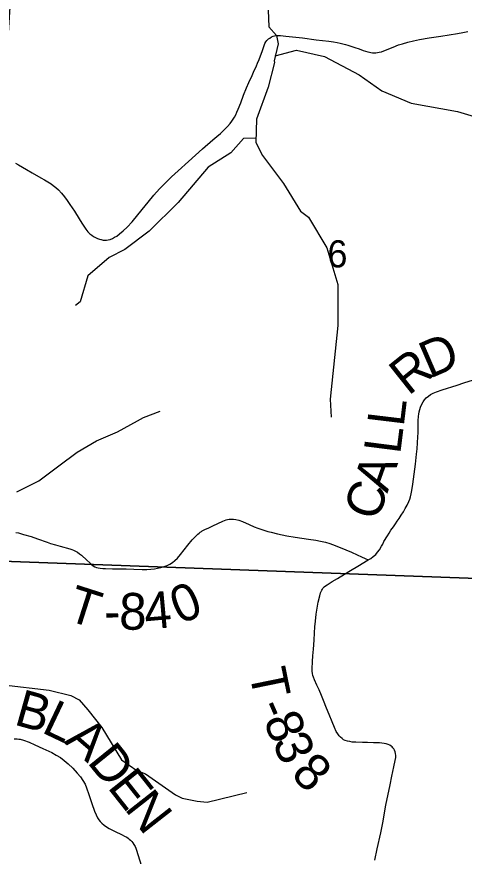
# Model space of a CAD drawing. Extents: x 0 to 34, y 0 to 22.
# Drawn here: x 6.26 to 6.952, y 17.839 to 19.136 of the extents above; entities that cross this region are included whole.
import ezdxf

# ---------------------------------------------------------------- set-up
doc = ezdxf.new("R2010")
doc.units = 0
for name, color, linetype in [('GM_X_County_Road', 7, 'Continuous'), ('GM_X_County_Road_Text', 7, 'Continuous'), ('GM_X_Minor_River', 7, 'Continuous'), ('GM_X_Section', 7, 'Continuous'), ('GM_X_Section_Text', 7, 'Continuous'), ('GM_X_Township_Road', 7, 'Continuous'), ('GM_X_Township_Road_Text', 7, 'Continuous')]:
    doc.layers.add(name, color=color, linetype=linetype)

msp = doc.modelspace()

# ---------------------------------------------------------------- linework, layer by layer
at = {"layer": 'GM_X_County_Road'}
msp.add_lwpolyline([(6.2558, 18.0204), (6.2601, 18.0202), (6.2627, 18.0199), (6.2649, 18.0194), (6.2703, 18.0179), (6.2786, 18.0149), (6.2876, 18.011), (6.2997, 18.0054), (6.3138, 17.9989), (6.3208, 17.9951), (6.3271, 17.9913), (6.333, 17.9869), (6.339, 17.9816), (6.3461, 17.9747), (6.3533, 17.9671), (6.358, 17.9613), (6.3619, 17.9558), (6.3652, 17.9499), (6.3677, 17.9443), (6.3712, 17.9342), (6.3758, 17.9203), (6.3801, 17.9086), (6.3824, 17.9027), (6.3847, 17.8982), (6.3867, 17.895), (6.3887, 17.8925), (6.3914, 17.8897), (6.3947, 17.8868), (6.3983, 17.8843), (6.4026, 17.8817), (6.4109, 17.8773), (6.4227, 17.8717), (6.4262, 17.8699), (6.4296, 17.8681), (6.4318, 17.8667), (6.4337, 17.8653), (6.4355, 17.8637), (6.4375, 17.8616), (6.4391, 17.8597), (6.4408, 17.8571), (6.4425, 17.854), (6.4437, 17.8513), (6.4449, 17.8483), (6.4521, 17.8252)], dxfattribs=at)
at = {"layer": 'GM_X_Minor_River'}
for points in [[(6.6482, 19.1461), (6.6494, 19.1199), (6.6611, 19.107), (6.6638, 19.0937), (6.6578, 19.0675), (6.6581, 19.0652), (6.6483, 19.0268), (6.6302, 18.9774), (6.6295, 18.9416), (6.6394, 18.9215), (6.6719, 18.8782), (6.6984, 18.8354), (6.7109, 18.8259), (6.7393, 18.7787)], [(6.6593, 19.0751), (6.6921, 19.0842), (6.7353, 19.0745), (6.7889, 19.0462), (6.8244, 19.0211), (6.8696, 19.0022), (6.9414, 18.9893), (6.9875, 18.9753), (7.0485, 18.9684), (7.0623, 18.9634), (7.0755, 18.9607)], [(6.6297, 18.9482), (6.6102, 18.9478), (6.5906, 18.9253), (6.5555, 18.9031), (6.5091, 18.849), (6.4646, 18.8043), (6.4269, 18.776), (6.4026, 18.7638), (6.3694, 18.7355), (6.3575, 18.6952), (6.3503, 18.6895)], [(6.7392, 18.7787), (6.7559, 18.7219), (6.7563, 18.6588), (6.7442, 18.5449), (6.7456, 18.5172)], [(6.2596, 18.4018), (6.2936, 18.4186), (6.3245, 18.4419), (6.3529, 18.4632), (6.3827, 18.4808), (6.4156, 18.4946), (6.4462, 18.5117), (6.4557, 18.5167), (6.4814, 18.5263)], [(6.0056, 18.2259), (6.014, 18.201), (6.037, 18.1745), (6.0614, 18.1595), (6.1024, 18.1517), (6.1803, 18.1301), (6.2389, 18.1034), (6.3096, 18.0954), (6.3434, 18.0872), (6.3563, 18.0805), (6.3693, 18.065), (6.3911, 18.0377), (6.4214, 17.9878), (6.4451, 17.9712), (6.4587, 17.9659), (6.5049, 17.9335), (6.5155, 17.9283), (6.5387, 17.9238), (6.5539, 17.9224), (6.6153, 17.9371)]]:
    msp.add_lwpolyline(points, dxfattribs=at)
at = {"layer": 'GM_X_Section'}
for points in [[(6.2595, 19.3129), (7.3152, 19.2658), (7.2546, 18.2574), (6.1942, 18.2962)], [(6.1942, 18.2962), (7.2546, 18.2574), (7.1862, 17.219), (6.1312, 17.2799)]]:
    msp.add_lwpolyline(points, close=True, dxfattribs=at)
at = {"layer": 'GM_X_Township_Road'}
for points in [[(6.3895, 18.7916), (6.3904, 18.7914), (6.3933, 18.7908), (6.396, 18.7906), (6.3986, 18.7906), (6.401, 18.791), (6.4041, 18.7917), (6.4076, 18.7932), (6.4109, 18.795), (6.4142, 18.797), (6.4186, 18.8002), (6.4242, 18.805), (6.4304, 18.8107), (6.4379, 18.8187), (6.4534, 18.8379), (6.4629, 18.8495), (6.4717, 18.8601), (6.4805, 18.8701), (6.4894, 18.8794), (6.4987, 18.8883), (6.509, 18.8975), (6.5251, 18.9121), (6.547, 18.9315), (6.5629, 18.9454), (6.5689, 18.9507), (6.5746, 18.9556), (6.5809, 18.9614), (6.5857, 18.9662), (6.5896, 18.9709), (6.5923, 18.9744), (6.5945, 18.9776), (6.5964, 18.9808), (6.5983, 18.9843), (6.6001, 18.9884), (6.6021, 18.993), (6.6059, 19.0028), (6.6103, 19.0144), (6.615, 19.0259), (6.6187, 19.0344), (6.6235, 19.0452), (6.6258, 19.0503), (6.6302, 19.0599), (6.6319, 19.0639), (6.6344, 19.0695), (6.6367, 19.0756), (6.639, 19.0823), (6.6422, 19.0911), (6.6435, 19.0942), (6.6449, 19.0968), (6.6466, 19.0992), (6.6488, 19.1014), (6.6508, 19.1029), (6.6535, 19.1045), (6.6559, 19.1055), (6.6581, 19.1061), (6.6605, 19.1066), (6.664, 19.1068), (6.6674, 19.1067), (6.6759, 19.1059), (6.6858, 19.1049), (6.7016, 19.1031), (6.7226, 19.1002), (6.7423, 19.0978), (6.7497, 19.0968), (6.755, 19.0958), (6.7599, 19.0947), (6.764, 19.0938), (6.768, 19.0928), (6.7715, 19.0919), (6.7779, 19.0899), (6.7826, 19.0883), (6.7891, 19.0861), (6.7955, 19.0838), (6.8026, 19.0815), (6.805, 19.0809), (6.8074, 19.0804), (6.8098, 19.0802), (6.8122, 19.08), (6.8149, 19.0801), (6.8177, 19.0804), (6.8202, 19.0808), (6.8238, 19.0817), (6.8273, 19.0829), (6.8415, 19.0888), (6.8502, 19.0921), (6.856, 19.0941), (6.8642, 19.0965), (6.8731, 19.0986), (6.8822, 19.1004), (6.8975, 19.103), (6.9156, 19.1059), (6.9414, 19.1101), (6.9493, 19.1115), (6.957, 19.1127)], [(6.2577, 18.9093), (6.2623, 18.9069), (6.2687, 18.9031), (6.2746, 18.8997), (6.2833, 18.8948), (6.2967, 18.8871), (6.3026, 18.8836), (6.3126, 18.8774), (6.3161, 18.875), (6.32, 18.8719), (6.3241, 18.8681), (6.3287, 18.8631), (6.3334, 18.8573), (6.3375, 18.8518), (6.3419, 18.8458), (6.3488, 18.8353), (6.3559, 18.8234), (6.3602, 18.8167), (6.3664, 18.8075), (6.3696, 18.8037), (6.3727, 18.8006), (6.3755, 18.7983), (6.3783, 18.7964), (6.3815, 18.7946), (6.3845, 18.7933), (6.3876, 18.7921), (6.3895, 18.7916)], [(6.8133, 17.8328), (6.8171, 17.8504), (6.8224, 17.8747), (6.8255, 17.8906), (6.8306, 17.9178), (6.8369, 17.9491), (6.8397, 17.9625), (6.8429, 17.977), (6.845, 17.9868), (6.8456, 17.9911), (6.8457, 17.9942), (6.8454, 17.9973), (6.8447, 18.0003), (6.8437, 18.0026), (6.8425, 18.0048), (6.8413, 18.0064), (6.84, 18.0077), (6.8385, 18.009), (6.8367, 18.0102), (6.8339, 18.0115), (6.8309, 18.0125), (6.8278, 18.0131), (6.8244, 18.0136), (6.8205, 18.0139), (6.8111, 18.0142), (6.8018, 18.0144), (6.7944, 18.0145), (6.7838, 18.0148), (6.7783, 18.0152), (6.7745, 18.0158), (6.771, 18.0166), (6.7677, 18.0176), (6.7651, 18.0188), (6.7626, 18.0205), (6.7603, 18.0225), (6.7581, 18.0249), (6.7559, 18.0279), (6.7538, 18.0317), (6.7508, 18.0378), (6.7473, 18.0465), (6.7426, 18.058), (6.7387, 18.0678), (6.734, 18.0793), (6.7307, 18.0873), (6.7271, 18.0959), (6.7237, 18.1031), (6.7201, 18.1113), (6.7185, 18.1154), (6.7177, 18.1182), (6.717, 18.121), (6.7166, 18.1247), (6.7165, 18.1284), (6.7172, 18.1397), (6.7177, 18.1482), (6.7186, 18.1587), (6.7195, 18.1724), (6.7202, 18.1838), (6.7208, 18.1931), (6.7215, 18.2018), (6.7227, 18.213), (6.7241, 18.2222), (6.7259, 18.2313), (6.7281, 18.241), (6.7296, 18.2457), (6.7304, 18.2478), (6.7314, 18.2499), (6.7324, 18.2516), (6.7337, 18.2533), (6.7352, 18.2549), (6.7369, 18.2563), (6.7394, 18.258), (6.7473, 18.2631), (6.7558, 18.2681), (6.7732, 18.2787), (6.7895, 18.2886), (6.8007, 18.2951), (6.8032, 18.2966), (6.807, 18.299), (6.811, 18.3019), (6.8147, 18.3052), (6.8176, 18.3084), (6.8207, 18.3123), (6.8238, 18.3176), (6.8256, 18.3209), (6.8275, 18.3248), (6.8328, 18.3339), (6.8355, 18.3381), (6.8382, 18.3423), (6.842, 18.3479), (6.8452, 18.3525), (6.848, 18.3566), (6.8508, 18.3607), (6.8542, 18.3659), (6.8576, 18.3711), (6.8603, 18.3759), (6.8634, 18.3813), (6.8659, 18.387), (6.8673, 18.3906), (6.8685, 18.3942), (6.8697, 18.3985), (6.8707, 18.4036), (6.8721, 18.4135), (6.8742, 18.4289), (6.8762, 18.4446), (6.8779, 18.4597), (6.8788, 18.4683), (6.8795, 18.4776), (6.88, 18.4868), (6.8802, 18.493), (6.8804, 18.5035), (6.8806, 18.5116), (6.881, 18.5185), (6.8813, 18.522), (6.8819, 18.5253), (6.8828, 18.5288), (6.884, 18.5328), (6.8858, 18.537), (6.8879, 18.5408), (6.8901, 18.5438), (6.893, 18.547), (6.8963, 18.5498), (6.8994, 18.552), (6.9035, 18.5543), (6.9085, 18.5563), (6.9174, 18.5594), (6.9406, 18.5667), (6.9512, 18.57), (6.966, 18.5748)], [(6.2581, 18.339), (6.2623, 18.3382), (6.27, 18.3361), (6.2819, 18.3327), (6.2918, 18.3294), (6.3068, 18.324), (6.3119, 18.322), (6.3193, 18.3197), (6.3267, 18.3176), (6.3417, 18.3137), (6.3448, 18.3127), (6.3476, 18.3114), (6.3506, 18.31), (6.3535, 18.3083), (6.3565, 18.3062), (6.3598, 18.3037), (6.3681, 18.2961), (6.3724, 18.2919), (6.3751, 18.2894), (6.3779, 18.2873), (6.3803, 18.2859), (6.3829, 18.2849), (6.3855, 18.2842), (6.3887, 18.2837), (6.3926, 18.2833), (6.3968, 18.2831), (6.4075, 18.2829), (6.4191, 18.2829), (6.4288, 18.2828), (6.4407, 18.2822), (6.4537, 18.2818), (6.4606, 18.2819), (6.4672, 18.2823), (6.4724, 18.2829), (6.4772, 18.2836), (6.4825, 18.2848), (6.4876, 18.2863), (6.4922, 18.2881), (6.4963, 18.2901), (6.5004, 18.2925), (6.5043, 18.2956), (6.5081, 18.2995), (6.513, 18.3051), (6.5184, 18.3119), (6.5242, 18.3193), (6.5309, 18.3274), (6.5351, 18.3319), (6.5396, 18.3362), (6.5416, 18.3379), (6.5435, 18.3393), (6.5451, 18.3405), (6.5466, 18.3413), (6.5504, 18.3434), (6.5565, 18.3464), (6.5626, 18.3493), (6.5782, 18.3566), (6.5834, 18.3585), (6.5857, 18.3591), (6.5882, 18.3595), (6.5913, 18.3596), (6.595, 18.3595), (6.5986, 18.359), (6.6029, 18.358), (6.6087, 18.3559), (6.6189, 18.3514), (6.6268, 18.3479), (6.6326, 18.3456), (6.6402, 18.343), (6.6479, 18.3406), (6.6532, 18.3392), (6.6629, 18.3368), (6.6775, 18.3338), (6.6903, 18.3317), (6.711, 18.3286), (6.722, 18.327), (6.7293, 18.3257), (6.7369, 18.3239), (6.7438, 18.3218), (6.7522, 18.3189), (6.7686, 18.3124), (6.7771, 18.3087), (6.7862, 18.3043), (6.7927, 18.3013), (6.7985, 18.2987), (6.8032, 18.2966)]]:
    msp.add_lwpolyline(points, dxfattribs=at)

# ---------------------------------------------------------------- texts
at = {"layer": 'GM_X_County_Road_Text'}
for s, rotation, p in [('B', 344.2757, (6.2538, 18.0427)), ('L', 334.585, (6.2963, 18.0309)), ('A', 319.2812, (6.3314, 18.0149)), ('D', 308.9574, (6.3674, 17.9842)), ('E', 308.4476, (6.3987, 17.9454)), ('N', 308.071, (6.4251, 17.9122))]:
    msp.add_text(s, height=0.0568, rotation=rotation, dxfattribs=at).set_placement(p)
at = {"layer": 'GM_X_Section_Text'}
msp.add_text('6', height=0.0419, rotation=0, dxfattribs=at).set_placement((6.7399, 18.7485))
at = {"layer": 'GM_X_Township_Road_Text'}
for s, rotation, p in [('D', 23.3981, (6.8983, 18.5763)), ('R', 38.4867, (6.8652, 18.5493)), ('L', 83.1536, (6.8579, 18.5014)), ('L', 82.7316, (6.8525, 18.4588)), ('A', 70.3854, (6.8326, 18.3987)), ('C', 70.9646, (6.8174, 18.3547)), ('0', 22.7305, (6.5119, 18.1965)), ('T', 342.2776, (6.3344, 18.2044)), ('4', 5.1397, (6.4589, 18.1888)), ('8', 359.0556, (6.4177, 18.1891)), ('-', 1.3506, (6.3951, 18.1886)), ('T', 281.5419, (6.6187, 18.1238)), ('-', 293.6691, (6.6312, 18.0697)), ('8', 292.476, (6.6404, 18.0486)), ('3', 293.5432, (6.6542, 18.0152)), ('8', 315.7083, (6.6817, 17.9635))]:
    msp.add_text(s, height=0.0568, rotation=rotation, dxfattribs=at).set_placement(p)

doc.saveas('drawing.dxf')
